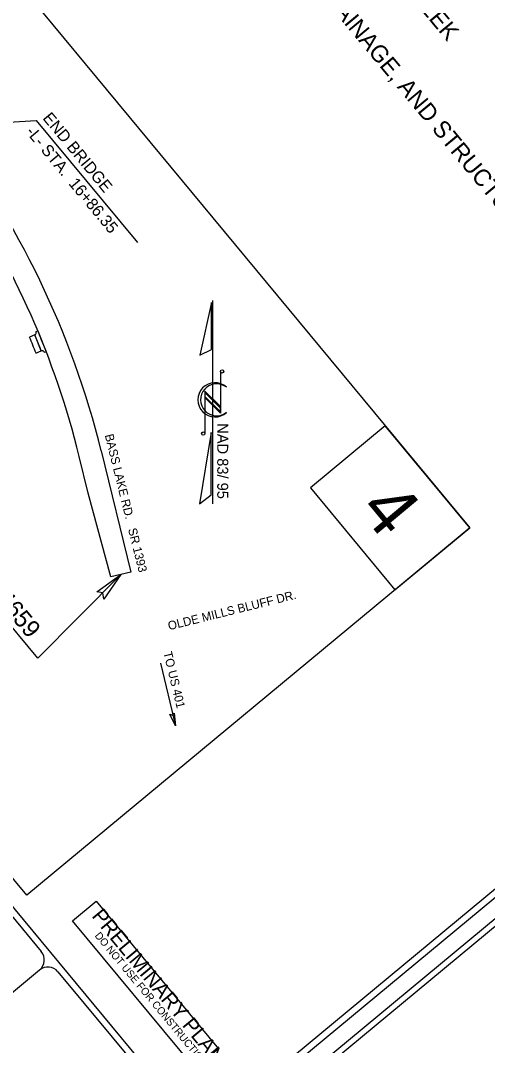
# Model space of a CAD drawing. Extents: x 2054826 to 2060231, y 685508 to 690809.
# Drawn here: x 2058981 to 2059519, y 687645 to 688824 of the extents above; entities that cross this region are included whole.
import ezdxf

# ---------------------------------------------------------------- set-up
doc = ezdxf.new("R2010")
doc.units = 0
for name, color, linetype in [('Default', 7, 'Continuous'), ('Old_Level_11', 7, 'Continuous'), ('Old_Level_21', 7, 'Continuous'), ('Old_Level_9', 7, 'Continuous'), ('Prop Dimension Text', 7, 'Continuous'), ('Prop Horizontal Alignment Station Label', 7, 'Continuous'), ('Prop Shade Medium', 7, 'Continuous'), ('Prop Terminator CELL', 7, 'Continuous'), ('Sheet Data Field CELL', 7, 'Continuous'), ('Sheet North Arrow CELL', 7, 'Continuous'), ('Sheet Plot Border Inside CELL', 7, 'Continuous'), ('Sheet Plot Border Outside CELL', 7, 'Continuous'), ('Sheet Sticker Preliminary CELL', 7, 'Continuous'), ('Sheet Title CELL', 7, 'Continuous')]:
    doc.layers.add(name, color=color, linetype=linetype)

msp = doc.modelspace()

# ---------------------------------------------------------------- linework, layer by layer
at = {"layer": 'Default'}
msp.add_line((2059142.5, 688084.6), (2059159.6, 688012.5), dxfattribs=at)
at = {"layer": 'Old_Level_21'}
for points in [[(2058588.3, 689338), (2059498.4, 688240.5), (2058988.4, 687817.6), (2058078.3, 688915.1)], [(2059498.4, 688240.5), (2059401.1, 688357.9), (2059314.9, 688286.4), (2059412.2, 688169)]]:
    msp.add_lwpolyline(points, close=True, dxfattribs=at)
at = {"layer": 'Prop Dimension Text'}
for p, q in [((2058880.3, 688701.4), (2058999.3, 688709.5)), ((2058999.3, 688709.5), (2059115.8, 688568.9))]:
    msp.add_line(p, q, dxfattribs=at)
at = {"layer": 'Prop Horizontal Alignment Station Label'}
for q in [(2058774.4, 688363.9), (2059096.8, 688186.9)]:
    msp.add_line((2059001.1, 688090.5), q, dxfattribs=at)
at = {"layer": 'Prop Shade Medium'}
for p, q in [((2058997.7, 688462.6), (2058991.7, 688460.1)), ((2058999.1, 688441.7), (2059005.2, 688444.1)), ((2059059.3, 688280.6), (2059048.9, 688322.8)), ((2059074.2, 688329), (2059108.4, 688189.7)), ((2059085.4, 688184.1), (2059059.3, 688280.6)), ((2059108.4, 688189.7), (2059085.4, 688184.1))]:
    msp.add_line(p, q, dxfattribs=at)
msp.add_lwpolyline([(2059010.9, 688443.1), (2059009, 688442.4), (2059008.8, 688442.8), (2059008.5, 688443.2), (2059008.3, 688443.4), (2059007.9, 688443.7), (2059007.5, 688444), (2059006.9, 688444.2), (2059006.5, 688444.3), (2059006, 688444.2), (2059005.4, 688444.2), (2059005.2, 688444.1), (2058997.7, 688462.6), (2058998.1, 688462.8), (2058998.7, 688463.2), (2058999, 688463.7), (2058999.3, 688464.3), (2058999.5, 688464.9), (2058999.5, 688465.5), (2058999.4, 688466.1), (2058999.3, 688466.5), (2059001.2, 688467.3)], close=True, dxfattribs=at)
for centre, radius, start, end in [((2058091.6, 688086.6), 1012, 13.8586, 37.5623), ((2058091.6, 688086.6), 986, 13.8586, 33.8372), ((2058091.6, 688086.7), 974.5, 21.3631, 22.5315), ((2058091.6, 688086.7), 981, 21.3631, 22.5315)]:
    msp.add_arc(centre, radius, start, end, dxfattribs=at)
at = {"layer": 'Prop Terminator CELL'}
for points in [[(2059069, 688166.9), (2059096.8, 688186.9), (2059077.3, 688158.5), (2059076, 688165.8)], [(2059158.2, 688027.4), (2059159.6, 688012.5), (2059153.2, 688026.2), (2059156.2, 688025)]]:
    msp.add_lwpolyline(points, close=True, dxfattribs=at)
at = {"layer": 'Sheet North Arrow CELL'}
for p, q in [((2059202.6, 688268), (2059202.6, 688502)), ((2059211.4, 688420.6), (2059211.4, 688372.5)), ((2059218, 688402.7), (2059218.3, 688402.5)), ((2059211.4, 688380), (2059193.5, 688397.9)), ((2059193.5, 688397.9), (2059193.5, 688349.1)), ((2059211.4, 688378.3), (2059193.5, 688396.2)), ((2059193.5, 688396.2), (2059193.5, 688391.8)), ((2059211.4, 688373.9), (2059193.5, 688391.8)), ((2059193.5, 688391.8), (2059211.4, 688373.9)), ((2059211.4, 688372.5), (2059193.5, 688390.4)), ((2059211.4, 688373.9), (2059211.4, 688378.3))]:
    msp.add_line(p, q, dxfattribs=at)
for points in [[(2059201, 688499.9), (2059187.6, 688439.2), (2059201, 688445.9)], [(2059200.7, 688350.4), (2059187.4, 688268), (2059200.7, 688278.4)]]:
    msp.add_lwpolyline(points, close=True, dxfattribs=at)
for centre in [(2059213.3, 688420.5), (2059191.6, 688349)]:
    msp.add_circle(centre, 1.91, dxfattribs=at)
for centre, radius, start, end in [((2059205.1, 688387.9), 19.7, 47.84, 312.3941), ((2059207, 688387.9), 18.4, 53.095, 308.6287)]:
    msp.add_arc(centre, radius, start, end, dxfattribs=at)
at = {"layer": 'Sheet Plot Border Inside CELL'}
msp.add_lwpolyline([(2057387.1, 689263.3), (2058982.8, 687339.1), (2060201, 688349.4), (2058605.4, 690273.6)], close=True, dxfattribs=at)
at = {"layer": 'Sheet Plot Border Outside CELL'}
msp.add_lwpolyline([(2060231.3, 688365.7), (2058618.8, 690310.1), (2057348.7, 689256.9), (2058961.2, 687312.4)], close=True, dxfattribs=at)
at = {"layer": 'Sheet Sticker Preliminary CELL'}
msp.add_lwpolyline([(2059041.1, 687788.3), (2059068.2, 687810.8), (2059209, 687641.1), (2059181.8, 687618.6)], close=True, dxfattribs=at)
at = {"layer": 'Sheet Title CELL'}
for p, q in [((2057819.1, 689194.8), (2059178.8, 687555.2)), ((2058813.9, 687983.5), (2059005.2, 687752.8)), ((2058818.5, 687578.5), (2059003.2, 687731.7)), ((2059024.4, 687729.7), (2059173, 687550.5))]:
    msp.add_line(p, q, dxfattribs=at)
for points in [[(2058985.3, 687365.6), (2060174.6, 688351.8)], [(2059199.9, 687553.3), (2060164, 688352.8)]]:
    msp.add_lwpolyline(points, dxfattribs=at)
for centre, start, end in [((2058993.7, 687743.2), 309.6672, 39.6672), ((2059012.8, 687720.1), 39.6672, 129.6672)]:
    msp.add_arc(centre, 15, start, end, dxfattribs=at)

# ---------------------------------------------------------------- texts
at = {"layer": 'Default'}
msp.add_text('BASS LAKE RD.   SR 1393', height=10, rotation=283.906, dxfattribs=at).set_placement((2059078.2, 688347.2))
at = {"layer": 'Old_Level_11'}
msp.add_text('4', height=61, rotation=309.7424, dxfattribs=at).set_placement((2059369.4, 688260.7))
at = {"layer": 'Old_Level_9'}
for s, rotation, p in [('OLDE MILLS BLUFF DR.', 13.906, (2059152.3, 688122.6)), ('TO US 401', 283.5418, (2059145.6, 688097))]:
    msp.add_text(s, height=10, rotation=rotation, dxfattribs=at).set_placement(p)
at = {"layer": 'Prop Dimension Text'}
for s, p in [('END BRIDGE', (2059006.1, 688711.7)), ('-L- STA.  16+86.35', (2058986.7, 688695.9))]:
    msp.add_text(s, height=13.5, rotation=309.6672, dxfattribs=at).set_placement(p)
at = {"layer": 'Prop Horizontal Alignment Station Label'}
msp.add_text('END TIP PROJECT B-4659 ', height=20, rotation=309.6672, dxfattribs=at).set_placement((2058779.1, 688367.3))
at = {"layer": 'Sheet Data Field CELL'}
for s, p in [('BRIDGE NO. 373 OVER BASAL CREEK ', (2059169.6, 689164.8)), ('GRADING, PAVING, DRAINAGE, AND STRUCTURE ', (2059158.3, 689056))]:
    msp.add_text(s, height=19.531, rotation=309.6672, dxfattribs=at).set_placement(p)
at = {"layer": 'Sheet North Arrow CELL'}
msp.add_text('NAD 83/ 95', height=12.6, rotation=270, dxfattribs=at).set_placement((2059207.7, 688360.9))
at = {"layer": 'Sheet Sticker Preliminary CELL'}
for s, height, p in [('PRELIMINARY PLANS', 17.28, (2059062.5, 687793.4)), ('DO NOT USE FOR CONSTRUCTION', 8.64, (2059066.2, 687770.9))]:
    msp.add_text(s, height=height, rotation=309.6672, dxfattribs=at).set_placement(p)

doc.saveas('drawing.dxf')
